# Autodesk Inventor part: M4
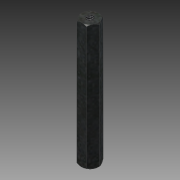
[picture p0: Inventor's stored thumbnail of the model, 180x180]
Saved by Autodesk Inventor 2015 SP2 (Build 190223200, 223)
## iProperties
Created: 2012-08
Part Number: M4
Material: Stahl
Document SubType Name: Modeling
Designer: rYan
Mass: 3.36246 g
Surface Area: 5.74911 cm^2
Volume: 0.428339 cm^3
Density: 7.85 g/cm^3
Appearance: Platte
Author: rYan
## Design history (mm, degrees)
derived "Abstandsbolzen Typ A.ipt"
feature "Volumenkörper1::Abstandsbolzen Typ A.ipt"
tag "Bezeichnung1"
node "Volumenkörper1"
other parameters: "SW" = 8, "d2" = 0, "d16" = 45 deg
